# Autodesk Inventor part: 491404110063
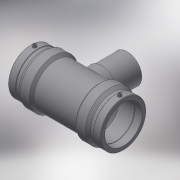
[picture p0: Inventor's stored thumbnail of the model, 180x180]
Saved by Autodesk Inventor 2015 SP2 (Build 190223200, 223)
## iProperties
Created: 2017-06
Part Number: 491404110063
Material: Generic
Description: PLASSON REDUCING TEE 110x63x110
Document SubType Name: Modeling
Designer: KIM
Mass: 1845.51 g
Surface Area: 2836.78 cm^2
Volume: 1845.51 cm^3
Density: 1 g/cm^3
Appearance: Default
Author: KIM
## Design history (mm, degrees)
derived "491404.ipt"
feature "Solid1::491404.ipt"
tag "TaggingFeature1"
body "Solid1"
other parameters: "d0" = 326, "d2" = 143, "d3" = 71, "d4" = 65.2, "d5" = 128.7, "d6" = 104.5, "d8" = 168 deg, "d10" = 28.4, "d11" = 9.46667, "d13" = 326, "d14" = 17.6296, "d17" = 99, "d19" = 3.52592, "d20" = 168 deg, "d22" = 132.99, "d23" = 143, "d25" = 135 deg, "d26" = 228.2, "d29" = 81, "d30" = 15, "d31" = 130.4, "d34" = 5 deg, "d35" = 15, "d39" = 5 deg, "d41" = 4, "d42" = 14, "d43" = 0, "d45" = 4, "d46" = 6, "d47" = 0, "d48" = -134, "d49" = 63, "d51" = 0, "d52" = 50.4, "d54" = 0, "d55" = 128.7, "d56" = 143, "d57" = 114.1, "d58" = 135 deg, "d59" = 71, "d60" = 71, "d61" = 135 deg, "d62" = 134, "d72" = 148.33, "d73" = 74.165, "d74" = -134, "d75" = 66.15, "d77" = 0, "d78" = 50.4, "d80" = 0, "d81" = 63, "d82" = 62.5, "d83" = 0, "d84" = 3, "d85" = 0, "d86" = 23.66667, "d87" = 130.3302, "d88" = 9.46667, "d89" = 3, "d90" = 0, "L_" = 326, "L_1" = 71, "D_" = 143, "A_" = 81, "d_2" = 12, "H_" = 134, "d_1" = 63
